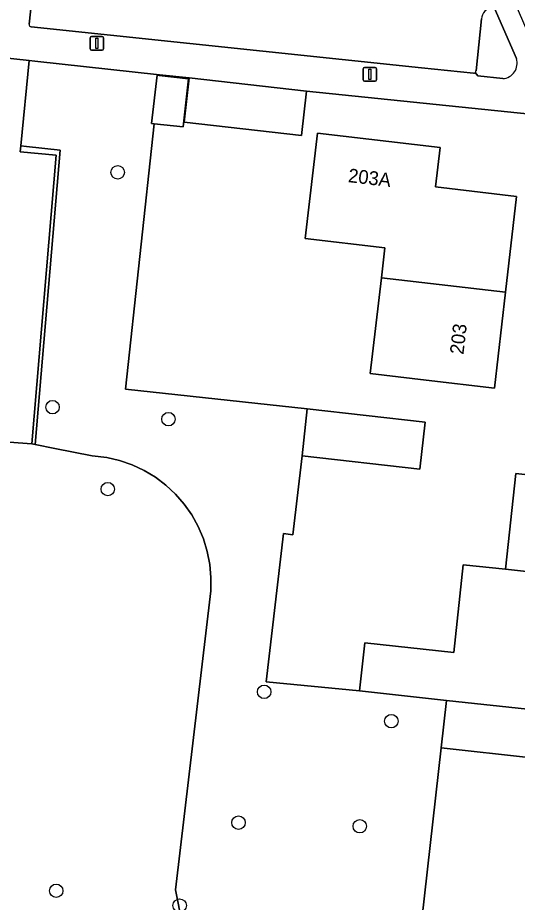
# Model space of a CAD drawing. Extents: x 162026 to 163502, y 387295 to 388169.
# Drawn here: x 162146.2 to 162182.6, y 387682.7 to 387747.1 of the extents above; entities that cross this region are included whole.
import ezdxf

# ---------------------------------------------------------------- set-up
doc = ezdxf.new("R2010")
doc.units = 0
for name, color, linetype in [('IMGEO_Boom', 7, 'Continuous'), ('IMGEO_Erf', 7, 'Continuous'), ('IMGEO_Groenvoorziening', 7, 'Continuous'), ('IMGEO_Haag', 7, 'Continuous'), ('IMGEO_Lichtmast', 7, 'Continuous'), ('IMGEO_Pand', 7, 'Continuous'), ('IMGEO_Pand_nummerreeks', 7, 'Continuous'), ('IMGEO_Parkeervlak_open', 7, 'Continuous'), ('IMGEO_Voetpad_open', 7, 'Continuous')]:
    doc.layers.add(name, color=color, linetype=linetype)

msp = doc.modelspace()

# ---------------------------------------------------------------- linework, layer by layer
at = {"layer": 'IMGEO_Boom'}
for centre in [(162153.527, 387735.834), (162148.78, 387718.744), (162157.222, 387717.87), (162152.802, 387712.779), (162164.197, 387698.025), (162173.459, 387695.89), (162162.328, 387688.506), (162171.165, 387688.24), (162149.048, 387683.545), (162158.041, 387682.471)]:
    msp.add_circle(centre, 0.489, dxfattribs=at)
at = {"layer": 'IMGEO_Erf'}
for points in [[(162184.532, 387739.974), (162167.28, 387741.736), (162166.917, 387738.524), (162158.361, 387739.491), (162158.724, 387742.703), (162156.565, 387742.938), (162156.558, 387742.875), (162158.683, 387742.635), (162158.288, 387739.138), (162156.181, 387739.376), (162154.1, 387720.065), (162167.342, 387718.615), (162175.916, 387717.646), (162175.53, 387714.231), (162166.956, 387715.2), (162166.286, 387709.462), (162165.595, 387709.554), (162164.333, 387698.759), (162171.154, 387698.087), (162171.533, 387701.59), (162178.016, 387700.889), (162178.707, 387707.274), (162181.769, 387706.943), (162182.523, 387713.915), (162186.768, 387713.456)], [(162183.684, 387693.225), (162177.095, 387693.938), (162175.073, 387676.073)]]:
    msp.add_lwpolyline(points, dxfattribs=at)
msp.add_lwpolyline([(162172.739, 387728.157), (162172.993, 387730.346), (162167.185, 387731.02), (162167.498, 387733.719), (162168.074, 387738.685), (162177.018, 387737.647), (162176.684, 387734.77), (162182.588, 387734.085), (162181.779, 387727.109), (162180.97, 387720.134), (162176.004, 387720.71), (162171.93, 387721.183)], close=True, dxfattribs=at)
at = {"layer": 'IMGEO_Groenvoorziening'}
for points in [[(162182.574, 387744.115), (162180.954, 387747.827)], [(162180.022, 387747.007), (162179.631, 387743.211)], [(162175.073, 387676.073), (162177.095, 387693.938), (162177.47, 387697.404), (162171.154, 387698.087), (162164.333, 387698.759), (162165.595, 387709.554), (162166.286, 387709.462), (162166.956, 387715.2), (162167.342, 387718.615), (162154.1, 387720.065), (162156.181, 387739.376), (162155.998, 387739.397), (162156.393, 387742.894), (162156.558, 387742.875), (162156.565, 387742.938), (162147.497, 387743.925), (162147.078, 387743.971), (162146.463, 387737.761), (162146.879, 387737.716), (162149.329, 387737.439), (162147.51, 387716.031), (162148.945, 387715.744), (162151.671, 387715.2), (162152.726, 387715.076), (162153.664, 387714.86), (162154.574, 387714.547), (162155.446, 387714.141), (162156.271, 387713.645), (162157.04, 387713.066), (162157.744, 387712.41), (162158.375, 387711.684), (162158.927, 387710.896), (162159.394, 387710.054), (162159.77, 387709.169), (162160.052, 387708.248), (162160.236, 387707.304), (162160.32, 387706.345), (162160.303, 387705.383), (162157.746, 387683.61), (162158.227, 387681.171)], [(162179.563, 387743.094), (162179.756, 387742.856), (162181.578, 387742.654)], [(162159.394, 387710.054), (162158.927, 387710.896), (162158.375, 387711.684), (162157.744, 387712.41), (162157.04, 387713.066), (162156.271, 387713.645), (162155.446, 387714.141), (162154.574, 387714.547), (162153.664, 387714.86), (162152.726, 387715.076), (162151.671, 387715.2), (162148.945, 387715.744), (162147.51, 387716.031), (162147.281, 387716.083), (162130.18, 387717.324), (162130.893, 387726.453), (162110.18, 387714.69)], [(162109.104, 387713.168), (162107.644, 387700.101), (162137.462, 387696.78), (162135.777, 387681.66), (162158.632, 387679.114), (162158.573, 387679.418), (162158.227, 387681.171), (162157.746, 387683.61), (162160.303, 387705.383), (162160.32, 387706.345), (162160.236, 387707.304), (162160.052, 387708.248), (162159.77, 387709.169), (162159.394, 387710.054)]]:
    msp.add_lwpolyline(points, dxfattribs=at)
msp.add_lwpolyline([(162149.329, 387737.439), (162146.879, 387737.716), (162146.463, 387737.761), (162146.42, 387737.324), (162149.048, 387737.072), (162147.281, 387716.083), (162147.51, 387716.031)], close=True, dxfattribs=at)
for centre, radius, start, end in [((162180.974, 387746.896), 0.958, 99.239, 173.35694), ((162181.504, 387743.774), 1.123, 273.77572, 17.65782), ((162179.428, 387743.25), 0.206, 310.69196, 348.97802)]:
    msp.add_arc(centre, radius, start, end, dxfattribs=at)
at = {"layer": 'IMGEO_Haag'}
msp.add_lwpolyline([(162149.329, 387737.439), (162146.879, 387737.716), (162146.463, 387737.761), (162146.42, 387737.324), (162149.048, 387737.072), (162147.281, 387716.083), (162147.51, 387716.031)], close=True, dxfattribs=at)
at = {"layer": 'IMGEO_Lichtmast'}
for p, q in [((162151.511, 387744.821), (162151.511, 387745.621)), ((162151.511, 387745.621), (162151.511, 387744.821)), ((162151.611, 387745.721), (162152.401, 387745.721)), ((162152.401, 387745.721), (162151.611, 387745.721)), ((162152.501, 387745.621), (162152.501, 387744.821)), ((162152.501, 387744.821), (162152.501, 387745.621)), ((162152.401, 387744.721), (162151.611, 387744.721)), ((162151.611, 387744.721), (162152.401, 387744.721)), ((162171.399, 387742.565), (162171.399, 387743.365)), ((162171.399, 387743.365), (162171.399, 387742.565)), ((162171.499, 387743.465), (162172.289, 387743.465)), ((162172.289, 387743.465), (162171.499, 387743.465)), ((162172.389, 387743.365), (162172.389, 387742.565)), ((162172.389, 387742.565), (162172.389, 387743.365)), ((162172.289, 387742.465), (162171.499, 387742.465)), ((162171.499, 387742.465), (162172.289, 387742.465))]:
    msp.add_line(p, q, dxfattribs=at)
for points in [[(162151.931, 387745.596), (162152.081, 387745.596), (162152.081, 387744.846), (162151.931, 387744.846), (162151.931, 387745.596)], [(162171.819, 387743.34), (162171.969, 387743.34), (162171.969, 387742.59), (162171.819, 387742.59), (162171.819, 387743.34)]]:
    msp.add_lwpolyline(points, dxfattribs=at)
for centre, start, end in [((162151.611, 387745.621), 90, 180), ((162151.611, 387745.621), 90, 180), ((162152.401, 387745.621), 0, 90), ((162152.401, 387745.621), 360, 90), ((162151.611, 387744.821), 180, 270), ((162151.611, 387744.821), 180, 270), ((162152.401, 387744.821), 270, 0), ((162152.401, 387744.821), 270, 0), ((162171.499, 387743.365), 90, 180), ((162171.499, 387743.365), 90, 180), ((162172.289, 387743.365), 0, 90), ((162172.289, 387743.365), 360, 90), ((162171.499, 387742.565), 180, 270), ((162171.499, 387742.565), 180, 270), ((162172.289, 387742.565), 270, 0), ((162172.289, 387742.565), 270, 0)]:
    msp.add_arc(centre, 0.1, start, end, dxfattribs=at)
at = {"layer": 'IMGEO_Pand'}
for points in [[(162156.558, 387742.875), (162156.393, 387742.894), (162155.998, 387739.397), (162156.181, 387739.376), (162158.288, 387739.138), (162158.683, 387742.635)], [(162158.724, 387742.703), (162158.361, 387739.491), (162166.917, 387738.524), (162167.28, 387741.736)], [(162181.779, 387727.109), (162182.588, 387734.085), (162176.684, 387734.77), (162177.018, 387737.647), (162168.074, 387738.685), (162167.498, 387733.719), (162167.185, 387731.02), (162172.993, 387730.346), (162172.739, 387728.157)], [(162172.739, 387728.157), (162171.93, 387721.183), (162176.004, 387720.71), (162180.97, 387720.134), (162181.779, 387727.109)], [(162166.956, 387715.2), (162175.53, 387714.231), (162175.916, 387717.646), (162167.342, 387718.615)], [(162190.985, 387705.945), (162191.739, 387712.919), (162186.768, 387713.456), (162182.523, 387713.915), (162181.769, 387706.943)], [(162190.912, 387705.271), (162190.985, 387705.945), (162181.769, 387706.943), (162178.707, 387707.274), (162178.016, 387700.889), (162171.533, 387701.59), (162171.154, 387698.087), (162177.47, 387697.404), (162184.059, 387696.699), (162184.373, 387699.601), (162190.231, 387698.968), (162190.402, 387700.549), (162191.023, 387700.482), (162191.479, 387701.207), (162191.824, 387704.398), (162191.534, 387705.204)], [(162184.059, 387696.699), (162177.47, 387697.404), (162177.095, 387693.938), (162183.684, 387693.225)]]:
    msp.add_lwpolyline(points, close=True, dxfattribs=at)
at = {"layer": 'IMGEO_Parkeervlak_open'}
for points in [[(162147.483, 387750.485), (162147.069, 387746.618)], [(162147.225, 387746.416), (162175.649, 387743.433), (162179.451, 387743.049)], [(162179.631, 387743.211), (162180.022, 387747.007)]]:
    msp.add_lwpolyline(points, dxfattribs=at)
for centre, radius, start, end in [((162180.974, 387746.896), 0.958, 99.239, 173.35694), ((162147.279, 387746.619), 0.21, 180.28382, 255.07237), ((162179.428, 387743.25), 0.206, 310.69196, 348.97802), ((162179.441, 387743.236), 0.187, 273.08013, 310.69898)]:
    msp.add_arc(centre, radius, start, end, dxfattribs=at)
at = {"layer": 'IMGEO_Voetpad_open'}
for points in [[(162146.618, 387751.565), (162144.468, 387751.76), (162143.866, 387746.385), (162141.359, 387746.642), (162141.091, 387744.623), (162144.592, 387744.242), (162144.823, 387744.217), (162147.078, 387743.971), (162147.497, 387743.925), (162156.565, 387742.938), (162158.724, 387742.703), (162167.28, 387741.736), (162184.532, 387739.974), (162190.357, 387726.536), (162212.606, 387674.544)], [(162147.069, 387746.618), (162147.483, 387750.485)], [(162205.878, 387698.65), (162204.156, 387697.934), (162198.251, 387711.7), (162199.955, 387712.383), (162198.263, 387716.306), (162196.55, 387715.597), (162188.179, 387734.99), (162189.885, 387735.684), (162188.222, 387739.573), (162186.488, 387738.87), (162182.655, 387747.763), (162180.954, 387747.827), (162182.574, 387744.115)], [(162179.451, 387743.049), (162175.649, 387743.433), (162147.225, 387746.416)], [(162130.893, 387726.453), (162130.18, 387717.324), (162147.281, 387716.083), (162149.048, 387737.072), (162146.42, 387737.324), (162146.463, 387737.761), (162147.078, 387743.971), (162144.823, 387744.217), (162144.109, 387737.41), (162131.948, 387738.529), (162131.182, 387729.497), (162131.078, 387728.269), (162109.421, 387716.064), (162109.104, 387713.168)], [(162181.578, 387742.654), (162179.756, 387742.856), (162179.563, 387743.094)]]:
    msp.add_lwpolyline(points, dxfattribs=at)
for centre, radius, start, end in [((162147.279, 387746.619), 0.21, 180.28382, 255.07237), ((162181.504, 387743.774), 1.123, 273.77572, 17.65782), ((162179.441, 387743.236), 0.187, 273.08013, 310.69898)]:
    msp.add_arc(centre, radius, start, end, dxfattribs=at)

# ---------------------------------------------------------------- texts
at = {"layer": 'IMGEO_Pand_nummerreeks'}
for s, rotation, p in [('203A', 353.38013, (162170.273, 387735.127)), ('203', 83.38407, (162178.712, 387722.543))]:
    msp.add_text(s, height=1, rotation=rotation, dxfattribs=at).set_placement(p)

doc.saveas('drawing.dxf')
